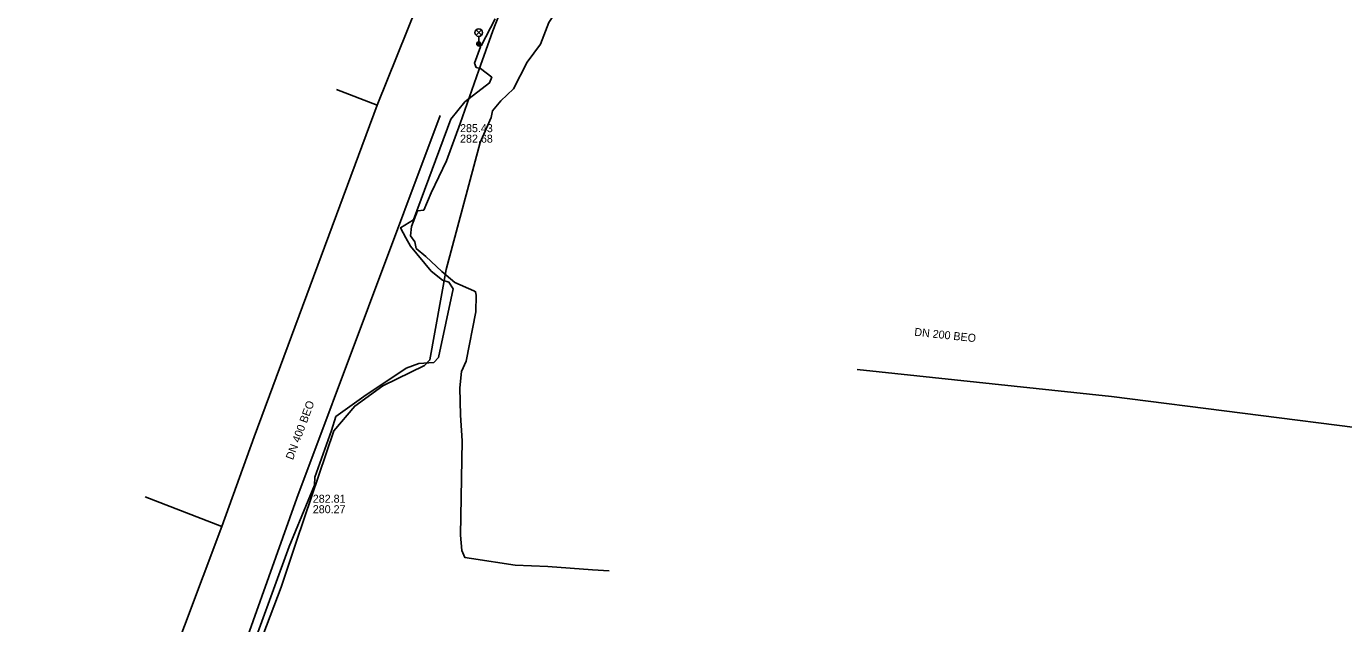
# Model space of a CAD drawing. Extents: x -595540 to -593988, y -1160850 to -1159202.
# Drawn here: x -594338.7 to -594207, y -1160655.8 to -1160596.1 of the extents above; entities that cross this region are included whole.
import ezdxf

# ---------------------------------------------------------------- set-up
doc = ezdxf.new("R2010")
doc.units = 0
for name, color, linetype in [('BVK-VODOVOD_trasa sítě', 7, 'Continuous'), ('CETIN_kabel podzemní', 7, 'Continuous'), ('DESTOVA-AREAL_popisy', 7, 'Continuous'), ('DESTOVA-AREAL_trasa sítě', 7, 'Continuous'), ('DESTOVA-NEPROVOZOVANA_popisy', 7, 'Continuous'), ('DESTOVA_trasa neprovozované sítě', 7, 'Continuous'), ('DSP-SDEL-VODAFONE_kabel', 7, 'Continuous'), ('TSB_kabel VO', 7, 'Continuous'), ('TSB_lampy VO', 7, 'Continuous')]:
    doc.layers.add(name, color=color, linetype=linetype)

msp = doc.modelspace()

# ---------------------------------------------------------------- linework, layer by layer
at = {"layer": 'BVK-VODOVOD_trasa sítě'}
for p, q in [((-594303.62, -1160604.02), (-594307.693, -1160602.447)), ((-594319.14, -1160646.13), (-594326.831, -1160643.187))]:
    msp.add_line(p, q, dxfattribs=at)
msp.add_lwpolyline([(-594292.658, -1160576.764), (-594303.62, -1160604.02), (-594315.91, -1160637.18), (-594319.14, -1160646.13), (-594334.09, -1160685.85), (-594339.729, -1160698.34), (-594373.62, -1160759.16), (-594404.485, -1160814.598), (-594408.34, -1160821.09), (-594414.6, -1160832.37), (-594420.45, -1160842.93), (-594420.622, -1160843.241)], dxfattribs=at)
at = {"layer": 'CETIN_kabel podzemní'}
for points in [[(-594290.41, -1160592.38), (-594292.07, -1160596.59), (-594293.47, -1160600.51), (-594295.32, -1160605.84), (-594296.7, -1160609.58), (-594298.22, -1160612.77), (-594298.96, -1160614.51), (-594299.58, -1160614.58), (-594300.19, -1160616.15), (-594300.28, -1160617.08), (-594299.85, -1160617.67), (-594299.72, -1160618.34), (-594298.74, -1160619.14), (-594297.16, -1160620.66), (-594295.86, -1160621.75), (-594293.97, -1160622.58), (-594293.78, -1160622.68), (-594293.71, -1160623.01), (-594293.755, -1160624.683)], [(-594294.716, -1160629.606), (-594293.755, -1160624.683)], [(-594294.716, -1160629.606), (-594295.192, -1160630.629), (-594295.37, -1160632.29), (-594295.3, -1160635.02), (-594295.12, -1160637.59), (-594295.3, -1160647), (-594295.16, -1160648.53), (-594294.86, -1160649.23), (-594294.18, -1160649.34), (-594289.83, -1160649.99), (-594286.55, -1160650.13), (-594282.1, -1160650.46), (-594280.42, -1160650.56)]]:
    msp.add_lwpolyline(points, dxfattribs=at)
at = {"layer": 'DESTOVA-AREAL_trasa sítě'}
for p, q in [((-594255.619, -1160630.438), (-594230.195, -1160633.131)), ((-594230.195, -1160633.131), (-594167.06, -1160641.17))]:
    msp.add_line(p, q, dxfattribs=at)
at = {"layer": 'DESTOVA-NEPROVOZOVANA_popisy'}
for p, q in [((-594295.334, -1160607.77), (-594295.334, -1160607.77)), ((-594310.059, -1160644.811), (-594310.059, -1160644.811))]:
    msp.add_line(p, q, dxfattribs=at)
at = {"layer": 'DESTOVA_trasa neprovozované sítě'}
msp.add_line((-594297.328, -1160605.049), (-594311.649, -1160643.316), dxfattribs=at)
msp.add_lwpolyline([(-594311.649, -1160643.316), (-594318.817, -1160663.437), (-594325.216, -1160681.4)], dxfattribs=at)
at = {"layer": 'DSP-SDEL-VODAFONE_kabel'}
for points in [[(-594327.4, -1160690.13), (-594325.66, -1160686.38), (-594320.35, -1160671.64), (-594316.63, -1160661.17), (-594313.22, -1160652.2), (-594311.69, -1160647.61), (-594307.97, -1160636.56), (-594305.86, -1160634.1), (-594303.06, -1160632.07), (-594298.88, -1160630.06), (-594298.35, -1160629.49), (-594296.72, -1160620.46), (-594293.33, -1160607.75), (-594292.24, -1160605.24), (-594292.1, -1160604.59), (-594291.27, -1160603.58), (-594289.98, -1160602.39), (-594288.64, -1160599.74), (-594287.29, -1160597.93), (-594286.45, -1160595.75), (-594284.12, -1160592.17)], [(-594286.45, -1160595.75), (-594287.29, -1160597.93), (-594288.64, -1160599.74), (-594289.98, -1160602.39), (-594291.27, -1160603.58), (-594292.1, -1160604.59), (-594292.24, -1160605.24), (-594293.33, -1160607.75), (-594296.72, -1160620.46), (-594298.35, -1160629.49), (-594298.88, -1160630.06), (-594303.06, -1160632.07), (-594305.86, -1160634.1), (-594307.97, -1160636.56), (-594311.69, -1160647.61), (-594313.22, -1160652.2), (-594316.63, -1160661.17)]]:
    msp.add_lwpolyline(points, dxfattribs=at)
at = {"layer": 'TSB_kabel VO'}
msp.add_lwpolyline([(-594291.83, -1160595.38), (-594293.24, -1160598.082), (-594293.343, -1160597.959), (-594293.472, -1160597.897), (-594293.435, -1160598.036), (-594293.294, -1160598.205), (-594293.89, -1160599.83), (-594293.71, -1160600.26), (-594293.28, -1160600.35), (-594292.16, -1160601.23), (-594292.39, -1160601.8), (-594294.87, -1160603.7), (-594296.27, -1160605.42), (-594299.98, -1160615.5), (-594301.28, -1160616.28), (-594300.74, -1160617.28), (-594300.28, -1160618.1), (-594298.21, -1160620.61), (-594297.09, -1160621.5), (-594296.45, -1160621.72), (-594296.01, -1160622.37), (-594297.49, -1160629.24), (-594297.96, -1160629.73), (-594299.47, -1160629.84), (-594300.73, -1160630.3), (-594304.94, -1160633.13), (-594307.74, -1160635.15), (-594308.2, -1160636.55), (-594309.86, -1160641.22), (-594309.9, -1160641.99), (-594312.42, -1160648.14), (-594317.001, -1160660.659)], dxfattribs=at)
at = {"layer": 'TSB_lampy VO'}
for p, q in [((-594293.737, -1160597.037), (-594293.207, -1160596.507)), ((-594293.737, -1160596.507), (-594293.207, -1160597.037)), ((-594293.737, -1160597.037), (-594293.207, -1160596.507)), ((-594293.737, -1160596.507), (-594293.207, -1160597.037)), ((-594293.472, -1160597.147), (-594293.472, -1160597.897)), ((-594293.472, -1160597.147), (-594293.472, -1160597.897))]:
    msp.add_line(p, q, dxfattribs=at)
for centre, radius in [((-594293.472, -1160596.772), 0.375), ((-594293.472, -1160596.772), 0.375), ((-594293.472, -1160597.897), 0.2), ((-594293.472, -1160597.897), 0.2), ((-594293.472, -1160597.897), 0.145), ((-594293.472, -1160597.897), 0.145), ((-594293.472, -1160597.897), 0.0876), ((-594293.472, -1160597.897), 0.0876)]:
    msp.add_circle(centre, radius, dxfattribs=at)

# ---------------------------------------------------------------- texts
at = {"layer": 'DESTOVA-AREAL_popisy'}
msp.add_text('DN 200 BEO', height=0.8, rotation=353.9533, dxfattribs=at).set_placement((-594249.947, -1160627.063))
at = {"layer": 'DESTOVA-NEPROVOZOVANA_popisy'}
for s, p in [('285.43', (-594295.334, -1160606.72)), ('282.68', (-594295.334, -1160607.77)), ('282.81', (-594310.059, -1160643.761)), ('280.27', (-594310.059, -1160644.811))]:
    msp.add_text(s, height=0.8, dxfattribs=at).set_placement(p)
msp.add_text('DN 400 BEO', height=0.8, rotation=69.4822, dxfattribs=at).set_placement((-594312.045, -1160639.538))

doc.saveas('drawing.dxf')
